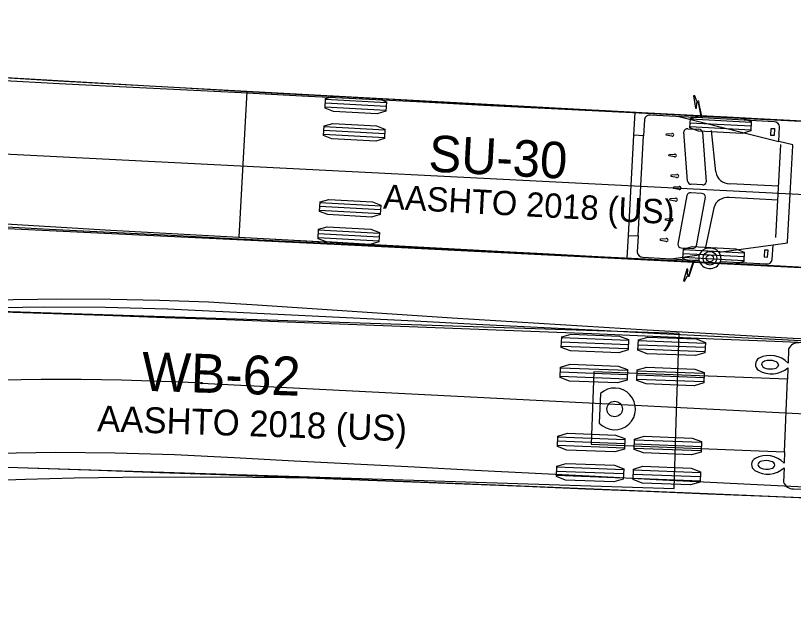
# Model space of a CAD drawing. Extents: x 260275 to 261282, y 610916 to 614143.
# Drawn here: x 261127.81 to 261170.38, y 611586.21 to 611618.9 of the extents above; entities that cross this region are included whole.
import ezdxf

# ---------------------------------------------------------------- set-up
doc = ezdxf.new("R2010")
doc.units = 0
doc.layers.add('UT_X_Water_Cells', color=7, linetype='Continuous')

msp = doc.modelspace()

# ---------------------------------------------------------------- linework, layer by layer
at = {"layer": 'UT_X_Water_Cells'}
for p, q in [((261066.343, 611614.434), (261269.731, 611604.069)), ((261148.105, 611614.122), (261144.777, 611614.302)), ((261148.083, 611613.706), (261144.754, 611613.886)), ((261148.094, 611613.914), (261144.765, 611614.094)), ((261164.115, 611613.364), (261169.577, 611612.002)), ((261168.074, 611613.046), (261164.745, 611613.216)), ((261148.013, 611612.416), (261144.684, 611612.597)), ((261148.024, 611612.624), (261144.696, 611612.805)), ((261164.599, 611612.702), (261165.214, 611612.669)), ((261168.053, 611612.63), (261164.724, 611612.8)), ((261168.064, 611612.838), (261164.735, 611613.008)), ((261166.13, 611610.332), (261165.907, 611612.611)), ((261169.139, 611612.336), (261169.159, 611612.714)), ((261169.159, 611612.714), (261169.353, 611612.704)), ((261169.353, 611612.704), (261169.333, 611612.326)), ((261148.002, 611612.208), (261144.673, 611612.389)), ((261161.352, 611606.858), (261161.649, 611612.342)), ((261161.882, 611606.829), (261162.179, 611612.313)), ((261163.423, 611612.341), (261163.427, 611612.423)), ((261163.72, 611612.289), (261163.423, 611612.341)), ((261163.427, 611612.423), (261163.728, 611612.443)), ((261164.593, 611609.822), (261164.387, 611612.531)), ((261165.408, 611612.506), (261165.613, 611609.797)), ((261169.333, 611612.326), (261169.139, 611612.336)), ((261169.416, 611606.748), (261169.692, 611611.845)), ((261163.577, 611611.296), (261163.892, 611611.316)), ((261163.572, 611611.214), (261163.577, 611611.296)), ((261163.884, 611611.162), (261163.572, 611611.214)), ((261163.694, 611610.089), (261163.698, 611610.171)), ((261163.991, 611610.037), (261163.694, 611610.089)), ((261163.698, 611610.171), (261164, 611610.191)), ((261165.402, 611609.626), (261164.786, 611609.66)), ((261169.567, 611609.546), (261166.903, 611609.69)), ((261163.827, 611609.432), (261163.831, 611609.515)), ((261164.124, 611609.38), (261163.827, 611609.432)), ((261163.831, 611609.515), (261164.133, 611609.534)), ((261163.624, 611608.794), (261163.628, 611608.876)), ((261163.921, 611608.742), (261163.624, 611608.794)), ((261163.628, 611608.876), (261163.93, 611608.896)), ((261164.55, 611609.044), (261164.054, 611606.373)), ((261165.376, 611609.152), (261164.76, 611609.185)), ((261165.071, 611606.288), (261165.568, 611608.959)), ((261169.526, 611608.782), (261166.862, 611608.926)), ((261147.787, 611608.256), (261144.459, 611608.436)), ((261147.799, 611608.464), (261144.47, 611608.644)), ((261166.023, 611608.372), (261165.554, 611606.118)), ((261147.776, 611608.048), (261144.448, 611608.228)), ((261163.381, 611607.688), (261163.386, 611607.771)), ((261163.679, 611607.636), (261163.381, 611607.688)), ((261163.386, 611607.771), (261163.687, 611607.79)), ((261147.718, 611606.966), (261144.389, 611607.146)), ((261147.695, 611606.55), (261144.367, 611606.73)), ((261147.706, 611606.758), (261144.378, 611606.938)), ((261163.111, 611606.584), (261163.115, 611606.667)), ((261163.115, 611606.667), (261163.417, 611606.686)), ((261163.408, 611606.532), (261163.111, 611606.584)), ((261166.303, 611605.933), (261169.27, 611606.339)), ((261163.693, 611605.575), (261165.228, 611605.785)), ((261164.245, 611606.181), (261164.861, 611606.147)), ((261167.679, 611605.682), (261164.35, 611605.851)), ((261167.689, 611605.89), (261164.36, 611606.059)), ((261168.799, 611606.054), (261168.778, 611605.676)), ((261168.992, 611606.043), (261168.799, 611606.054)), ((261168.972, 611605.665), (261168.992, 611606.043)), ((261167.668, 611605.474), (261164.339, 611605.643)), ((261166.392, 611605.429), (261168.91, 611605.292)), ((261168.778, 611605.676), (261168.972, 611605.665)), ((261161.363, 611601.099), (261157.699, 611601.239)), ((261161.345, 611600.641), (261157.681, 611600.781)), ((261161.354, 611600.87), (261157.69, 611601.01)), ((261165.551, 611600.71), (261161.887, 611600.85)), ((261165.56, 611600.939), (261161.896, 611601.079)), ((261165.542, 611600.481), (261161.878, 611600.621)), ((261170.118, 611600.644), (261170.089, 611599.869)), ((261161.3, 611599.45), (261157.636, 611599.59)), ((261165.497, 611599.29), (261161.833, 611599.43)), ((261161.282, 611598.992), (261157.618, 611599.132)), ((261161.291, 611599.221), (261157.627, 611599.361)), ((261165.479, 611598.832), (261161.815, 611598.972)), ((261165.488, 611599.061), (261161.824, 611599.201)), ((261169.903, 611595.011), (261170.055, 611598.982)), ((261137.985, 611598.767), (261278.274, 611591.618)), ((261159.821, 611598.193), (261159.759, 611596.578)), ((261161.147, 611595.441), (261157.483, 611595.58)), ((261161.155, 611595.67), (261157.491, 611595.809)), ((261165.352, 611595.509), (261161.688, 611595.649)), ((261161.138, 611595.212), (261157.474, 611595.351)), ((261165.335, 611595.051), (261161.671, 611595.191)), ((261165.344, 611595.28), (261161.68, 611595.42)), ((261161.084, 611593.792), (261157.42, 611593.932)), ((261161.092, 611594.021), (261157.428, 611594.161)), ((261165.289, 611593.86), (261161.625, 611594)), ((261169.869, 611594.124), (261169.84, 611593.349)), ((261161.075, 611593.563), (261157.411, 611593.703)), ((261165.272, 611593.402), (261161.608, 611593.542)), ((261165.281, 611593.631), (261161.617, 611593.771))]:
    msp.add_line(p, q, dxfattribs=at)
for points in [[(261084.592, 611618.899), (261087.2, 611618.596), (261092.438, 611618.047), (261097.699, 611617.562), (261102.977, 611617.126), (261108.268, 611616.728), (261113.567, 611616.359), (261124.183, 611615.684), (261134.814, 611615.063), (261156.1, 611613.904), (261198.699, 611611.699)], [(261126.839, 611615.525), (261130.162, 611615.33), (261133.485, 611615.139), (261136.809, 611614.951), (261140.134, 611614.766), (261143.459, 611614.583), (261146.785, 611614.402), (261150.111, 611614.223), (261153.438, 611614.046), (261156.765, 611613.869), (261160.092, 611613.694), (261163.42, 611613.519), (261166.748, 611613.346), (261170.075, 611613.172), (261173.403, 611613)], [(261126.87, 611615.354), (261130.188, 611615.185), (261133.507, 611615.016), (261136.828, 611614.847), (261140.15, 611614.678), (261143.473, 611614.508), (261146.797, 611614.339), (261150.122, 611614.17), (261153.447, 611614), (261156.773, 611613.831), (261160.099, 611613.661), (261163.426, 611613.492), (261166.753, 611613.322), (261170.08, 611613.152), (261173.408, 611612.983)], [(261162.228, 611613.211), (261162.18, 611612.316), (261162.176, 611612.313), (261161.65, 611612.341), (261161.649, 611612.353), (261161.716, 611613.594), (261140.461, 611614.745), (261140.245, 611610.751), (261140.028, 611606.757), (261161.284, 611605.605), (261161.351, 611606.847), (261161.353, 611606.858), (261161.879, 611606.829), (261161.882, 611606.826), (261161.834, 611605.931)], [(261165.142, 611614.189), (261165.095, 611614.192), (261165.094, 611614.193), (261164.979, 611614.494), (261164.914, 611614.498), (261164.914, 611614.495), (261165.017, 611613.832), (261165.018, 611613.829), (261165.074, 611613.826), (261165.074, 611613.829), (261165.1, 611614.145), (261165.1, 611614.146), (261165.145, 611614.143)], [(261165.164, 611614.13), (261165.164, 611614.13), (261165.339, 611613.302), (261165.327, 611613.298), (261162.557, 611613.448)], [(261169.332, 611613.081), (261165.405, 611613.294), (261165.393, 611613.301), (261165.212, 611614.144), (261165.212, 611614.145)], [(261169.227, 611605.529), (261169.27, 611606.336), (261169.275, 611606.34), (261170.053, 611606.447), (261170.058, 611606.489), (261170.201, 611609.128), (261170.344, 611611.768), (261170.344, 611611.81), (261169.582, 611612), (261169.577, 611612.005), (261169.621, 611612.812)], [(261188.635, 611604.191), (261146.014, 611606.327), (261124.68, 611607.337), (261113.994, 611607.802), (261103.282, 611608.218), (261097.908, 611608.4), (261092.517, 611608.561), (261087.099, 611608.697), (261081.645, 611608.809)], [(261126.365, 611607.539), (261129.697, 611607.344), (261133.029, 611607.152), (261136.36, 611606.964), (261139.692, 611606.778), (261143.022, 611606.595), (261146.353, 611606.414), (261149.683, 611606.235), (261153.013, 611606.057), (261156.343, 611605.88), (261159.672, 611605.705), (261163.002, 611605.53), (261166.331, 611605.356), (261169.66, 611605.183), (261172.99, 611605.011)], [(261126.319, 611607.373), (261129.658, 611607.203), (261132.996, 611607.032), (261136.333, 611606.862), (261139.669, 611606.692), (261143.003, 611606.522), (261146.337, 611606.352), (261149.669, 611606.182), (261153.002, 611606.013), (261156.333, 611605.843), (261159.665, 611605.673), (261162.995, 611605.503), (261166.326, 611605.333), (261169.656, 611605.164), (261172.986, 611604.994)], [(261162.135, 611605.659), (261164.905, 611605.509), (261164.917, 611605.504), (261164.653, 611604.7), (261164.653, 611604.7)], [(261164.7, 611604.68), (261164.7, 611604.681), (261164.971, 611605.499), (261164.983, 611605.505), (261165.211, 611605.493)], [(261164.633, 611604.689), (261164.588, 611604.691), (261164.588, 611604.692), (261164.596, 611605.009), (261164.596, 611605.012), (261164.541, 611605.015), (261164.54, 611605.012), (261164.365, 611604.364), (261164.365, 611604.362), (261164.43, 611604.358), (261164.577, 611604.645), (261164.577, 611604.646), (261164.625, 611604.644)], [(261083.782, 611604.207), (261089.045, 611603.958), (261094.338, 611603.746), (261104.974, 611603.382), (261118.308, 611602.962), (261119.643, 611602.935), (261122.321, 611603.122), (261124.998, 611603.258), (261127.674, 611603.345), (261130.349, 611603.384), (261133.023, 611603.374), (261135.695, 611603.316), (261138.365, 611603.211), (261141.033, 611603.058), (261151.703, 611602.341), (261162.373, 611601.688), (261170.375, 611601.234), (261181.049, 611600.761)], [(261115.943, 611594.555), (261115.943, 611594.532), (261163.847, 611592.993), (261163.984, 611597.24), (261164.121, 611601.488), (261116.216, 611603.028), (261116.215, 611603.006)], [(261125.917, 611602.883), (261129.32, 611602.942), (261132.726, 611602.926), (261136.133, 611602.834), (261139.531, 611602.677), (261142.914, 611602.509), (261146.289, 611602.341), (261149.657, 611602.172), (261153.02, 611602.002), (261156.377, 611601.832), (261159.731, 611601.662), (261163.082, 611601.492), (261166.43, 611601.322), (261169.775, 611601.152), (261173.118, 611600.981)], [(261125.982, 611602.712), (261129.32, 611602.6), (261132.657, 611602.486), (261135.995, 611602.369), (261139.333, 611602.25), (261142.67, 611602.128), (261146.008, 611602.003), (261149.345, 611601.875), (261152.682, 611601.746), (261156.019, 611601.613), (261159.356, 611601.478), (261162.692, 611601.341), (261166.029, 611601.202), (261169.365, 611601.061), (261172.701, 611600.918)], [(261170.079, 611599.612), (261170.055, 611598.982), (261159.463, 611599.386), (261159.311, 611595.415), (261169.903, 611595.011), (261169.879, 611594.381)], [(261126.742, 611594.933), (261129.999, 611594.979), (261133.254, 611594.951), (261136.505, 611594.852), (261139.768, 611594.688), (261143.05, 611594.516), (261146.34, 611594.345), (261149.637, 611594.174), (261152.939, 611594.004), (261156.246, 611593.835), (261159.557, 611593.665), (261162.871, 611593.495), (261166.188, 611593.326), (261169.508, 611593.156), (261172.829, 611592.987)], [(261125.701, 611594.216), (261129.033, 611594.105), (261132.364, 611593.991), (261135.695, 611593.874), (261139.026, 611593.755), (261142.357, 611593.633), (261145.687, 611593.509), (261149.018, 611593.382), (261152.349, 611593.252), (261155.679, 611593.12), (261159.01, 611592.985), (261162.341, 611592.849), (261165.672, 611592.71), (261169.003, 611592.569), (261172.334, 611592.426)], [(261176.331, 611592.251), (261165.672, 611592.71), (261155.013, 611593.147), (261144.355, 611593.559), (261139.021, 611593.616), (261133.684, 611593.602), (261131.015, 611593.563), (261128.345, 611593.497), (261125.674, 611593.402), (261123.002, 611593.274), (261120.328, 611593.107), (261117.653, 611592.897), (261114.976, 611592.646), (261112.297, 611592.353), (261109.616, 611592.021), (261106.932, 611591.652), (261104.246, 611591.246), (261101.555, 611590.808), (261098.86, 611590.337), (261096.16, 611589.839), (261090.739, 611588.77), (261088.696, 611588.35), (261087.322, 611587.861), (261084.559, 611586.816)], [(261170.384, 611592.978), (261175.462, 611592.784), (261175.079, 611592.076), (261175.078, 611592.076)]]:
    msp.add_lwpolyline(points, dxfattribs=at)
for points in [[(261148.108, 611614.174), (261148.08, 611613.655), (261147.605, 611613.523), (261145.209, 611613.653), (261144.751, 611613.835), (261144.78, 611614.354), (261145.254, 611614.485), (261147.65, 611614.355)], [(261168.077, 611613.098), (261168.05, 611612.578), (261167.576, 611612.446), (261165.179, 611612.568), (261164.721, 611612.748), (261164.748, 611613.267), (261165.222, 611613.4), (261167.619, 611613.278)], [(261148.027, 611612.676), (261147.999, 611612.157), (261147.524, 611612.026), (261145.128, 611612.155), (261144.67, 611612.337), (261144.698, 611612.856), (261145.173, 611612.987), (261147.569, 611612.858)], [(261147.802, 611608.515), (261147.773, 611607.996), (261147.299, 611607.865), (261144.902, 611607.995), (261144.445, 611608.176), (261144.473, 611608.696), (261144.948, 611608.827), (261147.344, 611608.697)], [(261147.72, 611607.018), (261147.692, 611606.498), (261147.218, 611606.367), (261144.821, 611606.497), (261144.364, 611606.679), (261144.392, 611607.198), (261144.866, 611607.329), (261147.263, 611607.199)], [(261167.692, 611605.941), (261167.665, 611605.422), (261167.191, 611605.289), (261164.795, 611605.411), (261164.336, 611605.592), (261164.363, 611606.111), (261164.837, 611606.244), (261167.234, 611606.122)], [(261161.365, 611601.156), (261161.343, 611600.584), (261160.823, 611600.431), (261158.185, 611600.532), (261157.679, 611600.724), (261157.701, 611601.296), (261158.22, 611601.448), (261160.858, 611601.347)], [(261165.562, 611600.995), (261165.54, 611600.424), (261165.02, 611600.271), (261162.382, 611600.372), (261161.876, 611600.564), (261161.898, 611601.135), (261162.417, 611601.288), (261165.055, 611601.187)], [(261161.302, 611599.507), (261161.28, 611598.935), (261160.761, 611598.783), (261158.122, 611598.883), (261157.616, 611599.075), (261157.638, 611599.647), (261158.157, 611599.799), (261160.796, 611599.699)], [(261165.499, 611599.347), (261165.477, 611598.775), (261164.957, 611598.622), (261162.319, 611598.723), (261161.813, 611598.915), (261161.835, 611599.487), (261162.354, 611599.639), (261164.992, 611599.538)], [(261161.158, 611595.726), (261161.136, 611595.155), (261160.616, 611595.002), (261157.978, 611595.103), (261157.472, 611595.295), (261157.494, 611595.866), (261158.013, 611596.019), (261160.651, 611595.918)], [(261165.354, 611595.566), (261165.333, 611594.994), (261164.813, 611594.842), (261162.175, 611594.943), (261161.669, 611595.134), (261161.69, 611595.706), (261162.21, 611595.859), (261164.848, 611595.758)], [(261161.095, 611594.078), (261161.073, 611593.506), (261160.553, 611593.353), (261157.915, 611593.454), (261157.409, 611593.646), (261157.431, 611594.217), (261157.95, 611594.37), (261160.588, 611594.269)], [(261165.292, 611593.917), (261165.27, 611593.346), (261164.75, 611593.193), (261162.112, 611593.294), (261161.606, 611593.486), (261161.628, 611594.057), (261162.147, 611594.21), (261164.785, 611594.109)]]:
    msp.add_lwpolyline(points, close=True, dxfattribs=at)
for centre, radius in [((261165.809, 611605.606), 0.374), ((261165.809, 611605.606), 0.193), ((261137.985, 611598.767), 0.0417), ((261137.985, 611598.767), 0.0417), ((261160.598, 611597.349), 0.424)]:
    msp.add_circle(centre, radius, dxfattribs=at)
for centre, radius, start, end in [((261165.176, 611614.166), 0.0418, 329.3921, 146.407), ((261165.177, 611614.172), 0.0434, 222.3139, 252.9866), ((261162.539, 611613.126), 0.323, 86.9002, 164.7486), ((261169.34, 611612.8), 0.282, 2.4486, 91.528), ((261164.571, 611612.52), 0.184, 81.4363, 176.3076), ((261165.218, 611612.476), 0.193, 9.0426, 90.9571), ((261163.743, 611612.377), 0.0909, 255.181, 349.4162), ((261163.742, 611612.353), 0.091, 4.4197, 98.5836), ((261163.892, 611611.226), 0.091, 4.4197, 98.5836), ((261163.893, 611611.25), 0.0909, 255.181, 349.4162), ((261164.015, 611610.124), 0.0909, 255.181, 349.4162), ((261164.013, 611610.101), 0.091, 4.4197, 98.5836), ((261166.891, 611610.463), 0.773, 189.7906, 270.8748), ((261164.783, 611609.852), 0.193, 189.0376, 270.962), ((261165.429, 611609.809), 0.184, 261.4419, 356.302), ((261164.148, 611609.468), 0.091, 255.2167, 349.3806), ((261164.146, 611609.444), 0.091, 4.4197, 98.5836), ((261164.736, 611608.994), 0.193, 82.8383, 164.7627), ((261163.945, 611608.83), 0.091, 255.2167, 349.3806), ((261163.943, 611608.806), 0.0909, 4.3841, 98.6193), ((261165.384, 611608.967), 0.184, 357.4983, 92.3584), ((261166.766, 611608.159), 0.773, 82.9255, 164.0097), ((261163.702, 611607.724), 0.091, 255.2167, 349.3806), ((261163.701, 611607.7), 0.0909, 4.3841, 98.6193), ((261163.43, 611606.596), 0.0909, 4.3841, 98.6193), ((261163.432, 611606.62), 0.091, 255.2167, 349.3806), ((261164.238, 611606.365), 0.184, 177.4927, 272.364), ((261164.885, 611606.339), 0.193, 262.8432, 344.7577), ((261162.152, 611605.982), 0.323, 189.0517, 266.9002), ((261165.722, 611605.61), 0.524, 139.1592, 192.9592), ((261165.798, 611605.537), 0.63, 86.255, 138.6578), ((261165.814, 611605.537), 0.629, 38.9457, 87.635), ((261165.895, 611605.601), 0.526, 340.8453, 39.0913), ((261165.813, 611605.673), 0.628, 196.6535, 337.1451), ((261168.948, 611605.572), 0.282, 262.2723, 351.3518), ((261164.662, 611604.663), 0.0418, 207.3933, 24.4082), ((261164.661, 611604.657), 0.0434, 100.8137, 131.4864), ((261170.637, 611600.403), 0.571, 84.7289, 155.1204), ((261169.12, 611598.938), 1.344, 43.8489, 117.4037), ((261168.691, 611599.793), 0.387, 119.309, 236.3179), ((261168.863, 611599.744), 0.228, 105.1158, 167.0106), ((261169.088, 611599.153), 0.86, 69.3794, 109.3488), ((261169.299, 611599.682), 0.29, 15.4577, 71.6178), ((261169.184, 611600.614), 1.344, 238.2232, 311.778), ((261168.897, 611599.848), 0.262, 191.6054, 258.1306), ((261169.134, 611600.421), 0.879, 250.6814, 285.2766), ((261169.339, 611599.819), 0.247, 276.2171, 346.0962), ((261130.35, 611448.962), 150, 87.08254, 113.79918), ((261160.598, 611597.355), 1.143, 222.8135, 132.8135), ((261168.91, 611593.45), 1.344, 43.8489, 117.4037), ((261168.473, 611594.306), 0.383, 118.2843, 237.3427), ((261168.683, 611594.235), 0.262, 97.4963, 164.0215), ((261168.657, 611594.342), 0.228, 188.6163, 250.5112), ((261168.876, 611593.646), 0.879, 70.3503, 104.9456), ((261169.126, 611594.231), 0.247, 9.5308, 79.4099), ((261168.974, 611595.126), 1.344, 238.2232, 311.778), ((261168.926, 611594.914), 0.86, 246.2781, 286.2475), ((261169.097, 611594.37), 0.29, 284.0092, 340.1692), ((261170.375, 611593.549), 0.571, 200.5065, 270.8981)]:
    msp.add_arc(centre, radius, start, end, dxfattribs=at)

# ---------------------------------------------------------------- texts
for s, height, rotation, p in [('SU-30', 2, 356.9002, (261150.381, 611610.362)), ('AASHTO 2018 (US)', 1.33333, 356.9002, (261147.91, 611608.326)), ('WB-62', 2.125, 358.1588, (261134.692, 611598.352)), ('AASHTO 2018 (US)', 1.41667, 358.1588, (261132.267, 611596.127))]:
    msp.add_text(s, height=height, rotation=rotation, dxfattribs=at).set_placement(p)

doc.saveas('drawing.dxf')
